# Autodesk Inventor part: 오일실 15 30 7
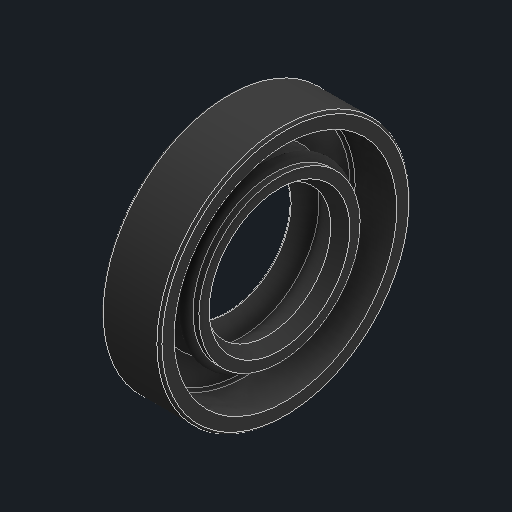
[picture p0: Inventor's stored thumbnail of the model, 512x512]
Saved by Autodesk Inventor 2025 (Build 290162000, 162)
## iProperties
Created: 2025-08
Part Number: 오일실 15 30 7
Material: 고무
Description: 오일-실
Document SubType Name: Modeling
Designer: infra005
Density: 0.93 g/cm^3
Appearance: 기본값
Author: jhkim
Sending System: Autodesk Inventor 2026
Preprocessor: ST-DEVELOPER v20.1
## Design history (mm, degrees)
feature "Solid1"
node "솔리드1"
